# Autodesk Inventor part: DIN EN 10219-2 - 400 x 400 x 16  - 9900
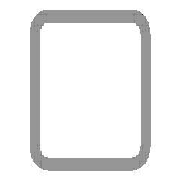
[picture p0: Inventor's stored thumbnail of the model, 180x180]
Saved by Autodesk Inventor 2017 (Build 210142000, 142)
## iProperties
IsCustomPart: 1
Created: 2017-11
Part Number: DIN EN 10219-2 - 400 x 400 x 16  - 9900
Material: Steel, Mild
Description: Cold formed welded structural hollow sections of non-alloy and fine grain structural steel
Document SubType Name: Modeling
Standard: DIN
Designer: iusti
Standard Revision: 2006-07
Standards Organization: DIN
Language: en-US
Size Designation: 400 x 400 x 16
Categories: <MemberInstance><Categories><Category DisplayName="Structural Shapes" InternalName="089c4875-fa83-4c05-b084-43b9cc11f5ed" Mnemonic="GRDR"><CategoryParameter Dis
Stock Number: 400 x 400 x 16
Density: 7.85 g/cm^3
Appearance: Semi-Polished
Mass: 1.76924e+06 g
Surface Area: 282196 cm^2
Volume: 225381 cm^3
_CCFamilyMember: 142
_CCFamilyDisplayName: DIN EN 10219-2 (Square Hollow Section - Cold Formed) - Cold formed welded structural hollow sections of non-alloy and fine grain structural steel
_FrameMemberDoc: Frame Member File
_Version: 15.0.0
_GetPNFromCC: 1
G_L: 9900.000 mm
G_W: 400.000 mm
G_H: 400.000 mm
+B9E1DA22-D309-4BBF-9627-4CE74C33B13E+CUTDETAIL1: Cut
+2FA9747E-09CC-4283-B5AE-DE9A0485B1EC+CUTDETAIL2: Cut
Author: iusti
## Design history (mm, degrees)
node "Start plane"
node "End plane"
sketch "Sketch"
  geometry: L1 (-200, -152)-(-200, 152); L2 (-152, 200)-(152, 200); L3 (200, 152)-(200, -152); L4 (152, -200)-(-152, -200); L5 (-152, 184)-(152, 184); L6 (184, 152)-(184, -152); L7 (152, -184)-(-152, -184); L8 (-184, -152)-(-184, 152); L9 (0, 293.918)-(0, -293.918) reference; L10 (-293.918, 0)-(293.918, 0) reference; A1 r 48 centre (-152, -152) between (-200, -152) and (-152, -200); A2 r 48 centre (-152, 152) between (-152, 200) and (-200, 152); A3 r 48 centre (152, 152) between (200, 152) and (152, 200); A4 r 48 centre (152, -152) between (152, -200) and (200, -152); A5 r 32 centre (-152, 152) between (-152, 184) and (-184, 152); A6 r 32 centre (152, 152) between (184, 152) and (152, 184); A7 r 32 centre (152, -152) between (152, -184) and (184, -152); A8 r 32 centre (-152, -152) between (-184, -152) and (-152, -184)
  constraints: 16 end point, 16 point on circle, 8 centre point, 8 tangent, 4 parallel, 3 equal radius, 2 perpendicular, 7 other
  dimensions: "d7" = 48 radius of A1 (= G_IR); "d10" = 400 distance between parallel lines of L2 L4 (= G_H); "d11" = 400 distance between parallel lines of L1 L3 (= G_W); "d12" = 16 distance between parallel lines of L3 L6 (= G_T); "d15" = 200 distance between parallel lines of L2 L10 (= 0.5 x d10); "d16" = 200 distance between parallel lines of L9 L3 (= 0.5 x d11)
extrude "Body" new body sketch "Sketch" stored distance "d3" = 9900 (= G_L); taper "d4" = 0 deg
node "Driven Length"
  sketch "Sketch3"
    geometry: L1 (0, 0)-(10, 0) reference
    constraints: 2 end point, 1 horizontal
  workplane "Work Plane3"
  sketch "Sketch4"
    geometry: L1 (-2, -200)-(12, -200) reference; L2 (-2, 9700)-(12, 9700) reference
    dimensions: "d18" = 9900 distance between parallel lines of L1 L2 (derived)
workplane "Work Plane4"
split "Split1"
workplane "Work Plane5"
split "Split2"
body "Solid1"
other parameters: "G_W" = 400 [user parameter; used in 1 equation term], "G_H" = 400 [user parameter; used in 1 equation term], "G_T" = 16 [user parameter; used in 1 equation term], "G_IR" = 48 [user parameter; used in 1 equation term], "G_L" = 9900 (= d18) [user parameter; used in 1 equation term], "d17" = 90 deg
